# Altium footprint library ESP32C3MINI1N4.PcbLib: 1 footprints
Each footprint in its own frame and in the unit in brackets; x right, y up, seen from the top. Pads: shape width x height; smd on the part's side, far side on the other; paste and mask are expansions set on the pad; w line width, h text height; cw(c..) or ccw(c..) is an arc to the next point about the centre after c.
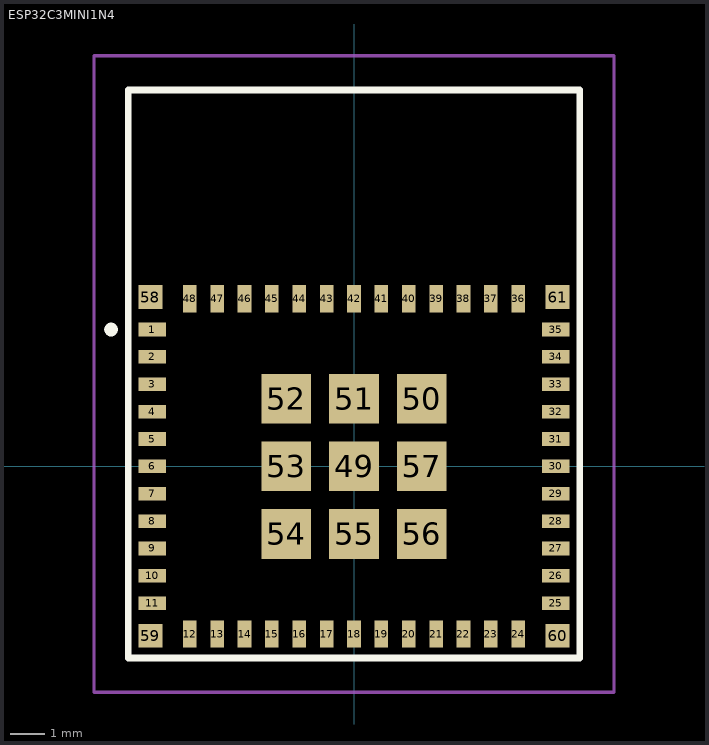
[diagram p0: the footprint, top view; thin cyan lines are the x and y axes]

## ESP32C3MINI1N4 [mm]
pads (61):
  rect 0.8x0.4 smd: 1(-5.9,4) 2(-5.9,3.2) 3(-5.9,2.4) 4(-5.9,1.6) 5(-5.9,0.8) 6(-5.9,0) 7(-5.9,-0.8) 8(-5.9,-1.6) 9(-5.9,-2.4) 10(-5.9,-3.2) 11(-5.9,-4) 25(5.9,-4) 26(5.9,-3.2) 27(5.9,-2.4) 28(5.9,-1.6) 29(5.9,-0.8) 30(5.9,0) 31(5.9,0.8) 32(5.9,1.6) 33(5.9,2.4) 34(5.9,3.2) 35(5.9,4)
  rect 0.4x0.8 smd: 12(-4.8,-4.9) 13(-4,-4.9) 14(-3.2,-4.9) 15(-2.4,-4.9) 16(-1.6,-4.9) 17(-0.8,-4.9) 18(0,-4.9) 19(0.8,-4.9) 20(1.6,-4.9) 21(2.4,-4.9) 22(3.2,-4.9) 23(4,-4.9) 24(4.8,-4.9) 36(4.8,4.9) 37(4,4.9) 38(3.2,4.9) 39(2.4,4.9) 40(1.6,4.9) 41(0.8,4.9) 42(0,4.9) 43(-0.8,4.9) 44(-1.6,4.9) 45(-2.4,4.9) 46(-3.2,4.9) 47(-4,4.9) 48(-4.8,4.9)
  rect 1.45x1.45 smd: 49(0,0) 50(1.975,1.975) 51(0,1.975) 52(-1.975,1.975) 53(-1.975,0) 54(-1.975,-1.975) 55(0,-1.975) 56(1.975,-1.975) 57(1.975,0)
  rect 0.7x0.7 smd: 58(-5.95,4.95) 59(-5.95,-4.95) 60(5.95,-4.95) 61(5.95,4.95)
Top Overlay:
  lines w0.2: -7.2,4 cw(c-7.1,4) -7,4 ; -7.2,4 -7.2,4 ; -7.2,4 ccw(c-7.1,4) -7,4 ; -7,4 -7,4 ; -6.6,-5.6 -6.6,5.7 -6.6,11 6.6,11 6.6,5.7 6.6,-5.6 -6.6,-5.6
Mechanical 15:
  lines w0.1: -6.6,-5.6 6.6,-5.6 6.6,11 -6.6,11 -6.6,-5.6
Mechanical 20:
  lines w0.1: -7.6,-6.6 7.6,-6.6 7.6,12 -7.6,12 -7.6,-6.6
